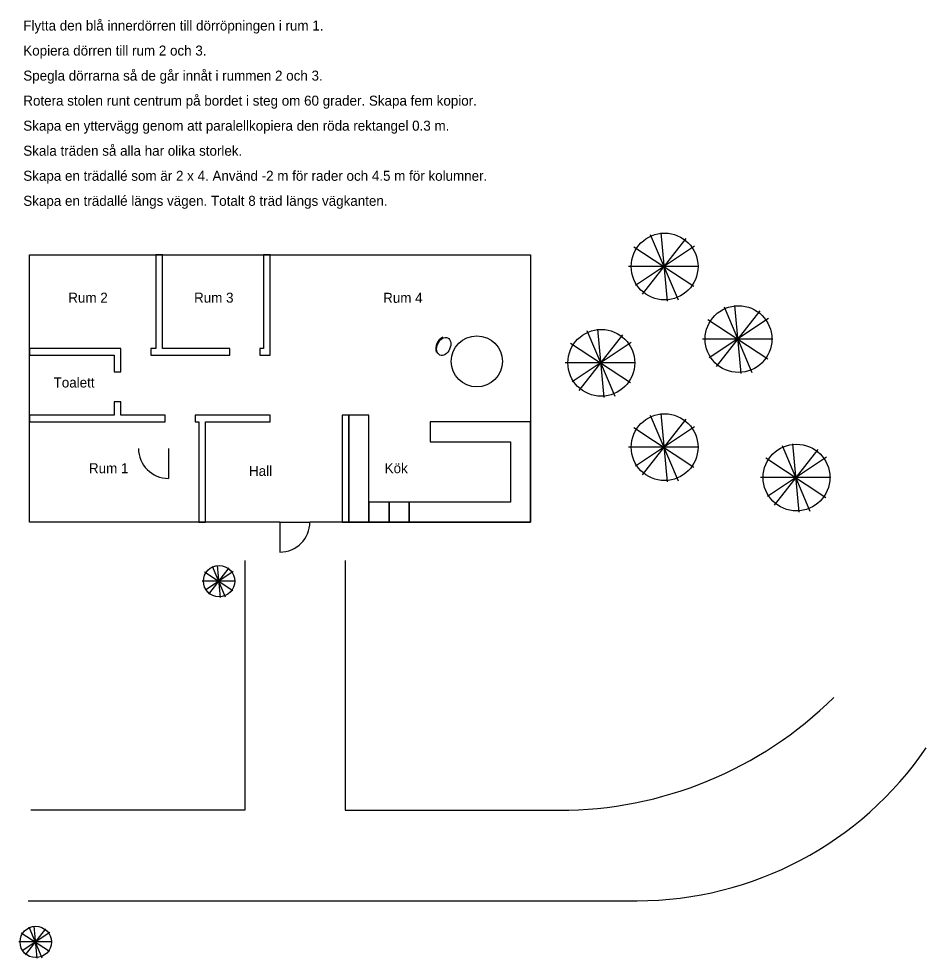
# Model space of a CAD drawing. Extents: x 1517703.6 to 1517730.8, y 6495348.8 to 6495376.9.
import ezdxf

# ---------------------------------------------------------------- set-up
doc = ezdxf.new("R2010")
doc.units = 0
doc.layers.add('Instruktioner', color=7, linetype='Continuous')
doc.layers.add('Lager 1', color=7, linetype='Continuous')

msp = doc.modelspace()

# ---------------------------------------------------------------- linework, layer by layer
at = {"layer": 'Instruktioner'}
for p, q in [((1517707.952, 6495367.063), (1517707.952, 6495369.863)), ((1517707.602, 6495366.863), (1517707.802, 6495366.863)), ((1517709.234, 6495364.863), (1517711.17, 6495364.863)), ((1517718.362, 6495364.263), (1517718.362, 6495362.463)), ((1517711.462, 6495361.863), (1517712.362, 6495361.863)), ((1517711.462, 6495361.863), (1517711.462, 6495360.963)), ((1517710.417, 6495360.711), (1517710.417, 6495353.23)), ((1517713.415, 6495360.711), (1517713.415, 6495353.231)), ((1517710.416, 6495353.229), (1517704.007, 6495353.229)), ((1517713.416, 6495353.23), (1517719.825, 6495353.23)), ((1517703.922, 6495350.521), (1517722.158, 6495350.521))]:
    msp.add_line(p, q, dxfattribs=at)
for points in [[(1517707.952, 6495369.863), (1517707.752, 6495369.863), (1517707.752, 6495367.063)], [(1517710.97, 6495366.863), (1517711.17, 6495366.863), (1517711.17, 6495369.863), (1517710.97, 6495369.863), (1517710.97, 6495367.063)], [(1517706.702, 6495366.863), (1517706.702, 6495367.063), (1517703.962, 6495367.063), (1517703.962, 6495366.863), (1517706.502, 6495366.863)], [(1517707.752, 6495367.063), (1517707.602, 6495367.063), (1517707.602, 6495366.863), (1517707.602, 6495366.863)], [(1517707.802, 6495366.863), (1517709.965, 6495366.863), (1517709.965, 6495367.063), (1517707.952, 6495367.063)], [(1517710.97, 6495367.063), (1517710.865, 6495367.063), (1517710.865, 6495366.863), (1517710.97, 6495366.863)], [(1517706.502, 6495366.863), (1517706.502, 6495366.363), (1517706.702, 6495366.363), (1517706.702, 6495366.863)], [(1517706.702, 6495365.063), (1517706.702, 6495365.463), (1517706.502, 6495365.463), (1517706.502, 6495365.063)], [(1517706.502, 6495365.063), (1517703.962, 6495365.063), (1517703.962, 6495364.863), (1517708.028, 6495364.863), (1517708.028, 6495365.063), (1517706.702, 6495365.063)], [(1517709.034, 6495365.063), (1517708.928, 6495365.063), (1517708.928, 6495364.863), (1517709.034, 6495364.863)], [(1517711.17, 6495364.863), (1517711.17, 6495365.063), (1517709.034, 6495365.063)], [(1517709.034, 6495364.863), (1517709.034, 6495361.863), (1517709.234, 6495361.863), (1517709.234, 6495364.863)], [(1517718.962, 6495364.263), (1517718.962, 6495364.863), (1517715.962, 6495364.863), (1517715.962, 6495364.263), (1517718.362, 6495364.263)], [(1517718.362, 6495361.863), (1517718.962, 6495361.863), (1517718.962, 6495364.263)], [(1517718.362, 6495362.463), (1517715.33, 6495362.463), (1517715.33, 6495361.863), (1517718.362, 6495361.863)]]:
    msp.add_lwpolyline(points, dxfattribs=at)
for points in [[(1517713.33, 6495361.863), (1517713.53, 6495361.863), (1517713.53, 6495365.063), (1517713.33, 6495365.063)], [(1517714.13, 6495365.063), (1517713.53, 6495365.063), (1517713.53, 6495361.863), (1517714.13, 6495361.863)], [(1517714.73, 6495362.463), (1517714.13, 6495362.463), (1517714.13, 6495361.863), (1517714.73, 6495361.863)], [(1517715.33, 6495362.463), (1517714.73, 6495362.463), (1517714.73, 6495361.863), (1517715.33, 6495361.863)]]:
    msp.add_lwpolyline(points, close=True, dxfattribs=at)
msp.add_circle((1517717.358, 6495366.675), 0.765, dxfattribs=at)
for centre, radius, start, end in [((1517711.462, 6495361.863), 0.9, 270, 0), ((1517719.825, 6495364.921), 11.691, 270, 314.6873), ((1517722.158, 6495360.99), 10.468, 270, 325.7567), ((1517710.416, 6495353.23), 0.001, 270, 0), ((1517713.416, 6495353.231), 0.001, 180, 270)]:
    msp.add_arc(centre, radius, start, end, dxfattribs=at)
at = {"layer": 'Lager 1'}
for p, q in [((1517722.548, 6495370.479), (1517723.381, 6495368.514)), ((1517722.863, 6495370.523), (1517723.053, 6495368.48)), ((1517722.061, 6495370.104), (1517723.859, 6495368.923)), ((1517723.874, 6495370.128), (1517722.108, 6495368.95)), ((1517723.614, 6495370.357), (1517722.311, 6495368.691)), ((1517724.009, 6495369.516), (1517721.899, 6495369.516)), ((1517725.826, 6495368.184), (1517724.523, 6495366.518)), ((1517724.76, 6495368.306), (1517725.593, 6495366.341)), ((1517725.074, 6495368.35), (1517725.264, 6495366.307)), ((1517724.273, 6495367.931), (1517726.071, 6495366.75)), ((1517726.086, 6495367.955), (1517724.319, 6495366.777)), ((1517720.653, 6495367.595), (1517721.485, 6495365.63)), ((1517720.967, 6495367.639), (1517721.157, 6495365.596)), ((1517721.718, 6495367.473), (1517720.415, 6495365.807)), ((1517726.221, 6495367.343), (1517724.111, 6495367.343)), ((1517720.165, 6495367.22), (1517721.963, 6495366.039)), ((1517721.978, 6495367.244), (1517720.212, 6495366.066)), ((1517722.113, 6495366.632), (1517720.003, 6495366.632)), ((1517722.548, 6495365.066), (1517723.381, 6495363.101)), ((1517722.863, 6495365.111), (1517723.053, 6495363.067)), ((1517723.614, 6495364.945), (1517722.311, 6495363.278)), ((1517722.061, 6495364.692), (1517723.859, 6495363.511)), ((1517723.874, 6495364.716), (1517722.108, 6495363.538)), ((1517726.812, 6495364.202), (1517727.002, 6495362.158)), ((1517708.128, 6495364.069), (1517708.128, 6495363.169)), ((1517724.009, 6495364.104), (1517721.899, 6495364.104)), ((1517727.563, 6495364.036), (1517726.26, 6495362.37)), ((1517726.498, 6495364.158), (1517727.33, 6495362.193)), ((1517726.01, 6495363.783), (1517727.808, 6495362.602)), ((1517727.824, 6495363.807), (1517726.057, 6495362.629)), ((1517727.958, 6495363.195), (1517725.848, 6495363.195)), ((1517709.438, 6495360.543), (1517709.828, 6495359.623)), ((1517709.586, 6495360.564), (1517709.675, 6495359.607)), ((1517709.21, 6495360.368), (1517710.052, 6495359.815)), ((1517710.06, 6495360.379), (1517709.232, 6495359.827)), ((1517709.938, 6495360.487), (1517709.327, 6495359.706)), ((1517710.123, 6495360.092), (1517709.134, 6495360.092)), ((1517703.721, 6495349.561), (1517704.564, 6495349.008)), ((1517704.571, 6495349.573), (1517703.743, 6495349.021)), ((1517704.449, 6495349.68), (1517703.839, 6495348.899)), ((1517703.95, 6495349.737), (1517704.34, 6495348.816)), ((1517704.097, 6495349.758), (1517704.186, 6495348.8)), ((1517704.634, 6495349.286), (1517703.646, 6495349.286))]:
    msp.add_line(p, q, dxfattribs=at)
msp.add_lwpolyline([(1517711.462, 6495361.863), (1517703.962, 6495361.863), (1517703.962, 6495369.863), (1517718.962, 6495369.863), (1517718.962, 6495361.863), (1517712.362, 6495361.863)], dxfattribs=at)
for centre, radius in [((1517722.98, 6495369.516), 1), ((1517725.191, 6495367.343), 1), ((1517721.084, 6495366.632), 1), ((1517722.98, 6495364.104), 1), ((1517726.929, 6495363.195), 1), ((1517709.641, 6495360.092), 0.469), ((1517704.152, 6495349.286), 0.469)]:
    msp.add_circle(centre, radius, dxfattribs=at)
for centre, radius, start, end in [((1517716.526, 6495367.05), 0.398, 118.1196, 193.9418), ((1517708.128, 6495364.069), 0.9, 180, 270)]:
    msp.add_arc(centre, radius, start, end, dxfattribs=at)
msp.add_ellipse((1517716.367, 6495367.123), major_axis=(0.117, 0.258), ratio=0.690069, dxfattribs=at)

# ---------------------------------------------------------------- texts
at = {"layer": 'Instruktioner'}
for s, p in [('Flytta den blå innerdörren till dörröpningen i rum 1.', (1517703.78, 6495376.583)), ('Kopiera dörren till rum 2 och 3.', (1517703.78, 6495375.833)), ('Spegla dörrarna så de går innåt i rummen 2 och 3.', (1517703.78, 6495375.083)), ('Rotera stolen runt centrum på bordet i steg om 60 grader. Skapa fem kopior.', (1517703.78, 6495374.333)), ('Skapa en yttervägg genom att paralellkopiera den röda rektangel 0.3 m.', (1517703.78, 6495373.583)), ('Skala träden så alla har olika storlek.', (1517703.78, 6495372.833)), ('Skapa en trädallé som är 2 x 4. Använd -2 m för rader och 4.5 m för kolumner.', (1517703.78, 6495372.083)), ('Skapa en trädallé längs vägen. Totalt 8 träd längs vägkanten.', (1517703.78, 6495371.333)), ('Rum 2', (1517705.127, 6495368.433)), ('Rum 3', (1517708.893, 6495368.433)), ('Rum 4', (1517714.554, 6495368.428)), ('Toalett', (1517704.688, 6495365.892)), ('Rum 1', (1517705.746, 6495363.324)), ('Kök', (1517714.599, 6495363.326)), ('Hall', (1517710.537, 6495363.244))]:
    msp.add_text(s, height=0.3, dxfattribs=at).set_placement(p)

doc.saveas('drawing.dxf')
